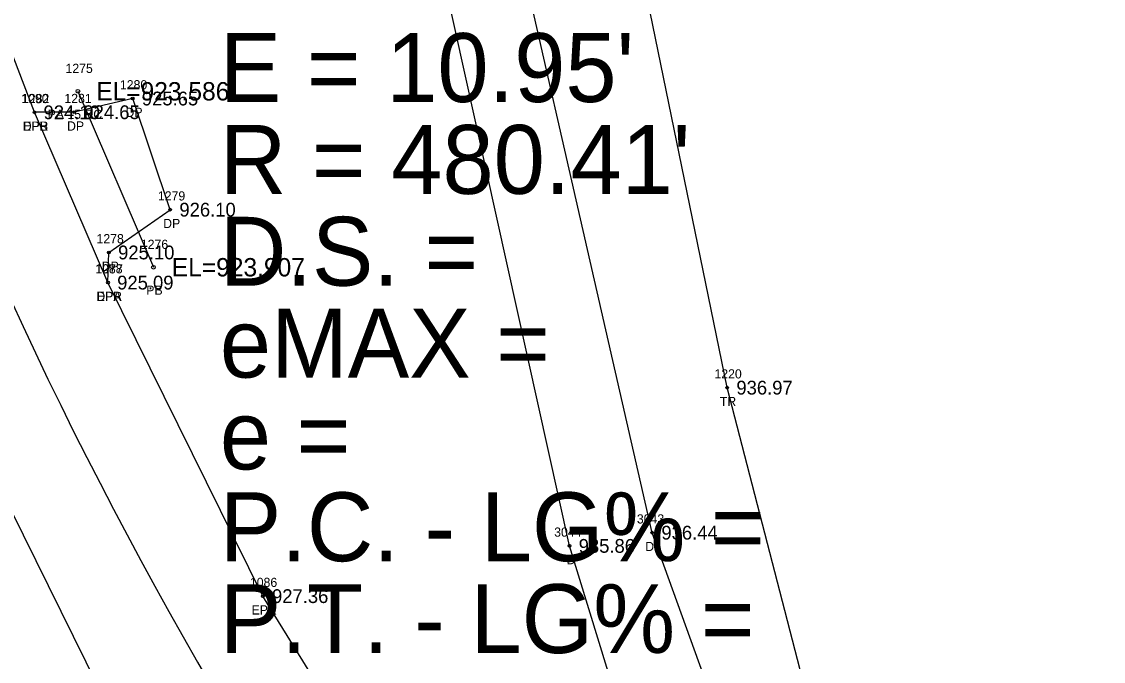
# Model space of a CAD drawing. Extents: x 1528109 to 1531398, y 1157799 to 1162548.
# Drawn here: x 1529933.4 to 1530051.3, y 1159401.1 to 1159470.8 of the extents above; entities that cross this region are included whole.
import ezdxf

# ---------------------------------------------------------------- set-up
doc = ezdxf.new("R2010")
doc.units = 0
for name, color, linetype in [('RD_EX_DR_Pipe', 7, 'Continuous'), ('RD_EX_DR_Pipe_txCode', 7, 'Continuous'), ('RD_EX_Driveway', 7, 'Continuous'), ('RD_EX_Driveway_txCode', 7, 'Continuous'), ('RD_EX_Road', 7, 'Continuous'), ('RD_EX_Road_txCode', 7, 'Continuous'), ('RD_EX_TX_Driveway_ELEV', 7, 'Continuous'), ('RD_EX_TX_Road_ELEV', 7, 'Continuous'), ('RD_EX_TX_VEG_ELEV', 7, 'Continuous'), ('RD_EX_VEG', 7, 'Continuous'), ('RD_EX_VEG_txCode', 7, 'Continuous'), ('RD_HC_Cl', 7, 'Continuous'), ('RD_HC_Data', 7, 'Continuous'), ('RD_SMD_Locator', 7, 'Continuous'), ('RD_TX_Pipe_ElevEX', 7, 'Continuous')]:
    doc.layers.add(name, color=color, linetype=linetype)

msp = doc.modelspace()

# ---------------------------------------------------------------- linework, layer by layer
at = {"layer": 'RD_EX_DR_Pipe'}
msp.add_line((1529939.53, 1159463.17), (1529947.76, 1159444.01), dxfattribs=at)
at = {"layer": 'RD_EX_Driveway'}
for points in [[(1530203.32, 1159298.84), (1530163.28, 1159286.11), (1530119.04, 1159286.75), (1530073.38, 1159307.7), (1530032.71, 1159350.36), (1530014.21, 1159381.53), (1530002.1, 1159415.11), (1529980.79, 1159508.48)], [(1530206.82, 1159287.58), (1530162.29, 1159275.2), (1530116.93, 1159276.42), (1530063.08, 1159301.27), (1530024.72, 1159342.07), (1530004.76, 1159375.72), (1529993.09, 1159413.67), (1529973.79, 1159500.74)], [(1529942.81, 1159442.34), (1529942.91, 1159445.62), (1529949.59, 1159450.28), (1529945.5, 1159462.38), (1529939.13, 1159460.89), (1529934.79, 1159460.88)]]:
    msp.add_lwpolyline(points, dxfattribs=at)
at = {"layer": 'RD_EX_Road'}
for points in [[(1530337.52, 1159156.44), (1530294.13, 1159166.93), (1530250.93, 1159177.7), (1530204.42, 1159191.5), (1530168.45, 1159204.97), (1530120.58, 1159231.54), (1530104.56, 1159243.15), (1530086.77, 1159257.61), (1530051.98, 1159290.88), (1530019.2, 1159326.18), (1529978.15, 1159378.31), (1529959.68, 1159408.2), (1529942.81, 1159442.34), (1529934.79, 1159460.88), (1529923.22, 1159491.09), (1529910.46, 1159527.95), (1529895.99, 1159570.93), (1529881.69, 1159613.98), (1529856.28, 1159690.67), (1529839.74, 1159739.71), (1529819.57, 1159800.04), (1529788.95, 1159890.99)], [(1530332.28, 1159136.67), (1530288.96, 1159147.06), (1530245.68, 1159158), (1530197.52, 1159172.18), (1530159.1, 1159186.57), (1530108.6, 1159214.89), (1530072.67, 1159242.37), (1530037.12, 1159276.96), (1530005.21, 1159311.5), (1529961.59, 1159366.88), (1529941.79, 1159398.29), (1529924.06, 1159434.11), (1529903.77, 1159484.39), (1529891.44, 1159520.8), (1529876.79, 1159564.7), (1529862.9, 1159606.82), (1529836.94, 1159684.29), (1529820.66, 1159733.09), (1529800.02, 1159794.4), (1529769.54, 1159884.46)]]:
    msp.add_lwpolyline(points, dxfattribs=at)
at = {"layer": 'RD_EX_VEG'}
msp.add_lwpolyline([(1530049.32, 1159334.73), (1530026.44, 1159368.44), (1530010.27, 1159430.9), (1529999.28, 1159484.57)], dxfattribs=at)
at = {"layer": 'RD_HC_Cl'}
msp.add_arc((1530368.9, 1159640.71), 480.41, 198.568, 222.8065, dxfattribs=at)
at = {"layer": 'RD_SMD_Locator'}
for centre, radius in [((1529939.53, 1159463.17), 0.2), ((1529945.5, 1159462.38), 0.15), ((1529934.79, 1159460.88), 0.15), ((1529934.79, 1159460.88), 0.15), ((1529939.13, 1159460.89), 0.15), ((1529949.59, 1159450.28), 0.15), ((1529942.91, 1159445.62), 0.15), ((1529947.76, 1159444.01), 0.2), ((1529942.81, 1159442.34), 0.15), ((1529942.81, 1159442.34), 0.15), ((1530010.27, 1159430.9), 0.15), ((1530002.1, 1159415.11), 0.15), ((1529993.09, 1159413.67), 0.15), ((1529959.68, 1159408.2), 0.15)]:
    msp.add_circle(centre, radius, dxfattribs=at)

# ---------------------------------------------------------------- texts
at = {"layer": 'RD_EX_DR_Pipe_txCode'}
for s, p in [('1275', (1529938.18, 1159465.17)), ('PA 15 RC', (1529936.23, 1159460.17)), ('1276', (1529946.39, 1159446.01)), ('PB', (1529946.98, 1159441.01))]:
    msp.add_text(s, height=1, dxfattribs=at).set_placement(p)
at = {"layer": 'RD_EX_Driveway_txCode'}
for s, p in [('1280', (1529944.11, 1159463.38)), ('1282', (1529933.44, 1159461.88)), ('1281', (1529938.06, 1159461.89)), ('DP', (1529944.72, 1159460.38)), ('DPB', (1529933.53, 1159458.88)), ('DP', (1529938.35, 1159458.89)), ('1279', (1529948.25, 1159451.28)), ('DP', (1529948.82, 1159448.28)), ('1278', (1529941.56, 1159446.62)), ('1277', (1529941.46, 1159443.34)), ('DP', (1529942.13, 1159443.62)), ('DPA', (1529941.54, 1159440.34)), ('3043', (1530000.43, 1159416.11)), ('3044', (1529991.42, 1159414.67)), ('D2', (1530001.34, 1159413.11)), ('D', (1529992.78, 1159411.67))]:
    msp.add_text(s, height=1, dxfattribs=at).set_placement(p)
at = {"layer": 'RD_EX_Road_txCode'}
for s, p in [('1090', (1529933.36, 1159461.88)), ('EPR', (1529933.56, 1159458.88)), ('1088', (1529941.42, 1159443.34)), ('EPR', (1529941.58, 1159440.34)), ('1086', (1529958.27, 1159409.2)), ('EPR', (1529958.45, 1159406.2))]:
    msp.add_text(s, height=1, dxfattribs=at).set_placement(p)
at = {"layer": 'RD_EX_TX_Driveway_ELEV'}
for s, p in [('925.65', (1529946.5, 1159461.63)), ('924.10', (1529935.79, 1159460.13)), ('924.65', (1529940.13, 1159460.14)), ('926.10', (1529950.59, 1159449.53)), ('925.10', (1529943.91, 1159444.87)), ('925.09', (1529943.81, 1159441.59)), ('936.44', (1530003.1, 1159414.36)), ('935.86', (1529994.09, 1159412.92))]:
    msp.add_text(s, height=1.5, dxfattribs=at).set_placement(p)
at = {"layer": 'RD_EX_TX_Road_ELEV'}
for s, p in [('924.10', (1529935.79, 1159460.13)), ('925.09', (1529943.81, 1159441.59)), ('927.36', (1529960.68, 1159407.45))]:
    msp.add_text(s, height=1.5, dxfattribs=at).set_placement(p)
at = {"layer": 'RD_EX_TX_VEG_ELEV'}
msp.add_text('936.97', height=1.5, dxfattribs=at).set_placement((1530011.27, 1159430.15))
at = {"layer": 'RD_EX_VEG_txCode'}
for s, p in [('1220', (1530008.88, 1159431.9)), ('TR', (1530009.47, 1159428.9))]:
    msp.add_text(s, height=1, dxfattribs=at).set_placement(p)
at = {"layer": 'RD_HC_Data'}
for s, p in [("E = 10.95'", (1529955, 1159462)), ("R = 480.41'", (1529955, 1159452)), ('D.S. = ', (1529955, 1159442)), ('eMAX = ', (1529955, 1159432)), ('e = ', (1529955, 1159422)), ('P.C. - LG% = ', (1529955, 1159412)), ('P.T. - LG% = ', (1529955, 1159402))]:
    msp.add_text(s, height=7.5, dxfattribs=at).set_placement(p)
at = {"layer": 'RD_TX_Pipe_ElevEX'}
for s, p in [('EL=923.586', (1529941.53, 1159462.17)), ('EL=923.907', (1529949.76, 1159443.01))]:
    msp.add_text(s, height=2, dxfattribs=at).set_placement(p)

doc.saveas('drawing.dxf')
